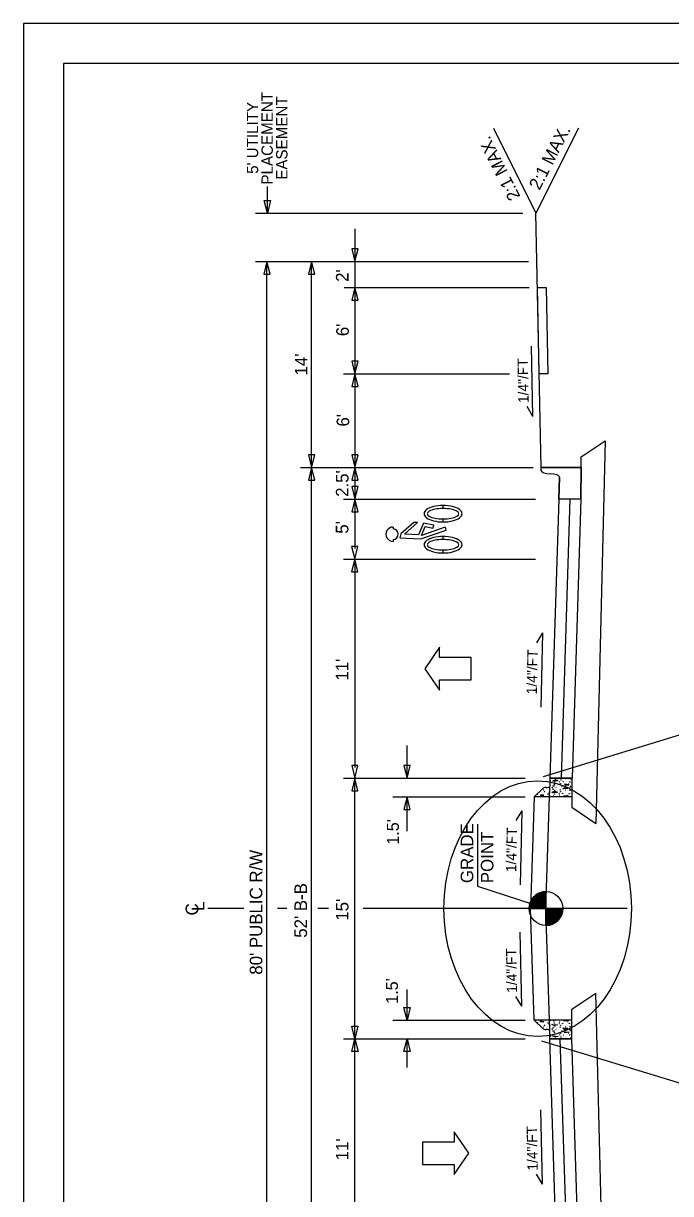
# Model space of a CAD drawing. Extents: x 0 to 8.5, y 0 to 11.
# Drawn here: x 0 to 4.02, y 3.73 to 11 of the extents above; entities that cross this region are included whole.
import ezdxf

# ---------------------------------------------------------------- set-up
doc = ezdxf.new("R2010")
doc.units = 0
for name, color, linetype in [('MARK BICYCLE SYMBOL CELL', 7, 'Continuous'), ('Old_Level_1', 7, 'Continuous'), ('Old_Level_11', 7, 'Continuous'), ('Old_Level_5', 7, 'Continuous'), ('PROP LANE ARROW CELL', 7, 'Continuous'), ('Prop Shade Light', 7, 'Continuous'), ('SHEET BORDER', 7, 'Continuous'), ('SHEET TRIM BORDER', 7, 'Continuous'), ('Typical Curb CELL', 7, 'Continuous'), ('Typical Grade Point Symbol CELL', 7, 'Continuous'), ('Typical Pavement Slope Information CELL', 7, 'Continuous')]:
    doc.layers.add(name, color=color, linetype=linetype)

msp = doc.modelspace()

# ---------------------------------------------------------------- linework, layer by layer
at = {"layer": 'MARK BICYCLE SYMBOL CELL'}
for p, q in [((2.609, 7.9845), (2.609, 8.0037)), ((2.609, 7.9845), (2.609, 8.0037)), ((2.2981, 7.8692), (2.2981, 7.8572)), ((2.2981, 7.8692), (2.2981, 7.8572)), ((2.4266, 7.8982), (2.3474, 7.8278)), ((2.3701, 7.8257), (2.451, 7.8982)), ((2.451, 7.8982), (2.4266, 7.8982)), ((2.4871, 7.8942), (2.456, 7.8205)), ((2.4743, 7.8161), (2.4981, 7.8727)), ((2.6225, 7.8683), (2.4743, 7.8161)), ((2.552, 7.8804), (2.4871, 7.8942)), ((2.4981, 7.8727), (2.5481, 7.8621)), ((2.5481, 7.8621), (2.552, 7.8804)), ((2.609, 7.9009), (2.609, 7.9201)), ((2.609, 7.9009), (2.609, 7.9201)), ((2.6287, 7.8507), (2.6245, 7.8689)), ((2.2981, 7.7924), (2.2981, 7.7804)), ((2.2981, 7.7924), (2.2981, 7.7804)), ((2.3474, 7.8278), (2.3399, 7.803)), ((2.3399, 7.803), (2.4714, 7.7953)), ((2.456, 7.8205), (2.3701, 7.8257)), ((2.4714, 7.7953), (2.6287, 7.8507)), ((2.609, 7.7916), (2.609, 7.8108)), ((2.609, 7.7916), (2.609, 7.8108)), ((2.609, 7.7081), (2.609, 7.7273)), ((2.609, 7.7081), (2.609, 7.7273))]:
    msp.add_line(p, q, dxfattribs=at)
for radius, start, end in [(0.0444, 90.00002, 270.00002), (0.0444, 90.00002, 270.00002), (0.0324, 270.00002, 90.00002)]:
    msp.add_arc((2.2981, 7.8248), radius, start, end, dxfattribs=at)
for centre, major_axis, ratio, start_param, end_param in [((2.609, 7.9523), (0.1179, 0), 0.435841, 1.570796, 4.712389), ((2.609, 7.9523), (0.1179, 0), 0.435841, 4.712389, 7.853982), ((2.609, 7.9523), (0.0987, 0), 0.325967, 1.570796, 4.712389), ((2.609, 7.9523), (0.0987, 0), 0.325967, 4.712389, 7.853982), ((2.609, 7.7594), (0.1179, 0), 0.435841, 1.570796, 4.712389), ((2.609, 7.7594), (0.0987, 0), 0.325967, 1.570796, 4.712389), ((2.609, 7.7594), (0.1179, 0), 0.435841, 4.712389, 7.853982), ((2.609, 7.7594), (0.0987, 0), 0.325967, 4.712389, 7.853982)]:
    msp.add_ellipse(centre, major_axis=major_axis, ratio=ratio, start_param=start_param, end_param=end_param, dxfattribs=at)
at = {"layer": 'Old_Level_1'}
for p, q in [((2.9224, 10.3496), (3.1867, 9.821)), ((3.4509, 10.3496), (3.1867, 9.821)), ((3.2196, 8.2386), (3.1867, 9.821)), ((3.4666, 8.3055), (3.6166, 8.4056)), ((3.6173, 8.406), (3.559, 6.0275)), ((3.4666, 8.2386), (3.4666, 8.3055)), ((3.4666, 8.2386), (3.2196, 8.2386)), ((3.2196, 8.219), (3.2196, 8.2386)), ((3.4665, 8.042), (3.4666, 8.2386)), ((3.4665, 8.042), (3.4666, 8.2386)), ((3.3331, 8.1795), (3.3287, 8.042)), ((3.3292, 8.042), (3.2727, 6.3088)), ((3.4665, 8.042), (3.3287, 8.042)), ((3.3973, 8.042), (3.3433, 6.3088)), ((3.4665, 8.042), (3.4125, 6.3088)), ((3.1749, 6.1915), (3.1531, 5.4983)), ((3.4096, 6.1915), (3.4096, 6.1271)), ((3.4096, 6.1271), (3.5596, 6.0271)), ((3.1749, 4.805), (3.1531, 5.4983)), ((3.4096, 4.8715), (3.5596, 4.9715)), ((3.6172, 2.5926), (3.559, 4.9711)), ((3.4096, 4.805), (3.4096, 4.8715)), ((3.3287, 2.9545), (3.2727, 4.6877)), ((3.393, 2.9545), (3.338, 4.6877)), ((3.4646, 2.9545), (3.4096, 4.6877))]:
    msp.add_line(p, q, dxfattribs=at)
for centre, major_axis, ratio, start_param, end_param in [((3.2784, 8.219), (0.059, 0), 0.333333, 3.141581, 4.664257), ((3.2728, 8.1797), (0.0603, 0), 0.32599, 6.272817, 7.805849)]:
    msp.add_ellipse(centre, major_axis=major_axis, ratio=ratio, start_param=start_param, end_param=end_param, dxfattribs=at)
at = {"layer": 'Old_Level_11'}
for p, q in [((1.5169, 9.821), (1.5169, 9.9854)), ((1.4438, 9.821), (3.104, 9.821)), ((2.0607, 9.7231), (2.0607, 9.2128)), ((1.4438, 9.5209), (3.1401, 9.521)), ((1.5138, 1.4756), (1.5135, 9.4997)), ((1.7921, 1.4756), (1.7921, 9.5209)), ((2.0607, 9.521), (2.0607, 9.2128)), ((1.9936, 9.3582), (3.144, 9.3583)), ((2.0607, 9.2128), (2.0607, 8.8217)), ((1.9907, 8.8216), (3.0231, 8.8217)), ((2.0607, 8.8216), (2.0607, 8.1993)), ((1.7225, 8.2386), (3.1697, 8.2386)), ((2.0607, 8.2386), (2.0606, 8.0419)), ((1.9906, 8.0419), (3.1837, 8.042)), ((2.0606, 8.0419), (2.0606, 7.7359)), ((1.9906, 7.6689), (3.1837, 7.669)), ((2.0597, 7.6689), (2.0596, 6.3754)), ((3.2343, 6.3179), (4.7141, 6.7735)), ((2.3851, 6.3082), (2.3851, 6.512)), ((1.9899, 6.3082), (3.1189, 6.3083)), ((2.0606, 4.6883), (2.0605, 6.3082)), ((3.2488, 5.4983), (3.2727, 6.2575)), ((2.2962, 6.1915), (3.1189, 6.1915)), ((2.3851, 5.9793), (2.3851, 6.1915)), ((2.8223, 6.0222), (2.8223, 5.6377)), ((2.8223, 5.6377), (3.2491, 5.4985)), ((1.3698, 5.4983), (1.1461, 5.4983)), ((1.6368, 5.4983), (1.5792, 5.4983)), ((1.8963, 5.4983), (1.8305, 5.4983)), ((3.7534, 5.4983), (2.1131, 5.4983)), ((3.2727, 4.739), (3.2488, 5.4983)), ((2.3851, 4.805), (2.3851, 4.9952)), ((2.2962, 4.805), (3.1188, 4.805)), ((1.9906, 4.6883), (3.1188, 4.6882)), ((2.0606, 3.3276), (2.0606, 4.6883)), ((2.3851, 4.5089), (2.3851, 4.6883)), ((3.221, 4.6764), (4.7706, 4.2022))]:
    msp.add_line(p, q, dxfattribs=at)
for points in [[(1.5366, 9.8996), (1.5169, 9.821), (1.4972, 9.8996)], [(2.041, 9.5996), (2.0607, 9.5209), (2.0804, 9.5996)], [(1.5335, 9.4422), (1.5138, 9.5209), (1.4941, 9.4422)], [(1.8117, 9.4422), (1.7921, 9.5209), (1.7724, 9.4422)], [(2.0804, 9.2796), (2.0607, 9.3582), (2.041, 9.2796)], [(2.041, 8.9003), (2.0607, 8.8217), (2.0803, 8.9003)], [(2.0803, 8.743), (2.0607, 8.8217), (2.041, 8.743)], [(1.7724, 8.3173), (1.7921, 8.2387), (1.8117, 8.3173)], [(2.041, 8.3173), (2.0607, 8.2386), (2.0803, 8.3173)], [(1.8118, 8.1599), (1.7921, 8.2386), (1.7724, 8.1599)], [(2.0803, 8.16), (2.0607, 8.2386), (2.041, 8.16)], [(2.041, 8.1206), (2.0606, 8.0419), (2.0803, 8.1206)], [(2.0803, 7.9632), (2.0606, 8.0419), (2.0409, 7.9632)], [(2.04, 7.7476), (2.0597, 7.6689), (2.0794, 7.7476)], [(2.0794, 7.5902), (2.0597, 7.6689), (2.04, 7.5902)], [(2.0409, 6.3869), (2.0605, 6.3082), (2.0802, 6.3869)], [(2.3654, 6.3869), (2.3851, 6.3082), (2.4048, 6.3869)], [(2.0802, 6.2296), (2.0605, 6.3082), (2.0409, 6.2296)], [(2.4048, 6.1128), (2.3851, 6.1915), (2.3654, 6.1128)], [(2.4048, 4.8837), (2.3851, 4.805), (2.3654, 4.8837)], [(2.0802, 4.7669), (2.0606, 4.6883), (2.0409, 4.7669)], [(2.0409, 4.6096), (2.0606, 4.6883), (2.0803, 4.6096)], [(2.3654, 4.6096), (2.3851, 4.6883), (2.4048, 4.6096)]]:
    msp.add_lwpolyline(points, close=True, dxfattribs=at)
msp.add_ellipse((3.1972, 5.4977), major_axis=(0.0013, -0.7944), ratio=0.733682, dxfattribs=at)
at = {"layer": 'Old_Level_5'}
for points in [[(3.2194, 8.219), (3.2196, 8.2386), (3.4666, 8.2386), (3.4665, 8.042), (3.3292, 8.042)], [(3.2757, 8.1993), (3.2756, 8.1993)], [(3.3292, 8.042), (3.3287, 8.042), (3.3331, 8.1795)]]:
    msp.add_lwpolyline(points, dxfattribs=at)
for centre, major_axis, ratio, start_param, end_param in [((3.2784, 8.219), (0.059, 0), 0.333333, 3.141581, 4.664257), ((3.2728, 8.1797), (0.0603, 0), 0.32599, 6.272817, 7.805849)]:
    msp.add_ellipse(centre, major_axis=major_axis, ratio=ratio, start_param=start_param, end_param=end_param, dxfattribs=at)
at = {"layer": 'PROP LANE ARROW CELL'}
for points in [[(2.586, 6.856), (2.586, 6.9193), (2.7832, 6.9193), (2.7832, 7.0587), (2.586, 7.0587), (2.586, 7.1221), (2.4953, 6.9877), (2.586, 6.856)], [(2.6783, 4.1099), (2.6783, 4.0465), (2.4811, 4.0465), (2.4811, 3.9071), (2.6783, 3.9071), (2.6783, 3.8438), (2.769, 3.9781), (2.6783, 4.1099)]]:
    msp.add_lwpolyline(points, dxfattribs=at)
at = {"layer": 'Prop Shade Light'}
msp.add_lwpolyline([(3.2074, 8.8217), (3.1963, 9.359), (3.2496, 9.3591), (3.2601, 8.8217)], close=True, dxfattribs=at)
at = {"layer": 'SHEET BORDER'}
msp.add_lwpolyline([(8.25, 10.75), (0.25, 10.75), (0.25, 0.25), (8.25, 0.25)], close=True, dxfattribs=at)
at = {"layer": 'SHEET TRIM BORDER'}
msp.add_lwpolyline([(8.5, 11), (0, 11), (0, 0), (8.5, 0)], close=True, dxfattribs=at)
at = {"layer": 'Typical Curb CELL'}
for p, q in [((3.2727, 6.3088), (3.4096, 6.3088)), ((3.2727, 6.3088), (3.2727, 6.2575)), ((3.4096, 6.3088), (3.2742, 6.3088)), ((3.3037, 6.2968), (3.29, 6.2904)), ((3.29, 6.2904), (3.3248, 6.2937)), ((3.3248, 6.2937), (3.3037, 6.2968)), ((3.3641, 6.2703), (3.3673, 6.2646)), ((3.3929, 6.2675), (3.3641, 6.2703)), ((3.3673, 6.2646), (3.3929, 6.2675)), ((3.4096, 6.3088), (3.4096, 6.1915)), ((3.2286, 6.2451), (3.1749, 6.1915)), ((3.4096, 6.1915), (3.1749, 6.1915)), ((3.2152, 6.203), (3.2152, 6.1963)), ((3.2354, 6.2026), (3.2152, 6.203)), ((3.2152, 6.1963), (3.2354, 6.2026)), ((3.2507, 6.2502), (3.2494, 6.2502)), ((3.3, 6.2249), (3.2863, 6.2185)), ((3.2863, 6.2185), (3.3213, 6.2217)), ((3.3213, 6.2217), (3.3, 6.2249)), ((3.3541, 6.2426), (3.3657, 6.2496)), ((3.3847, 6.245), (3.3541, 6.2426)), ((3.3604, 6.1984), (3.3636, 6.1927)), ((3.3891, 6.1956), (3.3604, 6.1984)), ((3.3636, 6.1927), (3.3891, 6.1956)), ((3.3657, 6.2496), (3.3847, 6.245)), ((3.4096, 4.805), (3.1749, 4.805)), ((3.2286, 4.7514), (3.1749, 4.805)), ((3.3604, 4.7981), (3.3636, 4.8038)), ((3.3891, 4.8009), (3.3604, 4.7981)), ((3.3636, 4.8038), (3.3891, 4.8009)), ((3.4096, 4.6877), (3.4096, 4.805)), ((3.2152, 4.7935), (3.2152, 4.8002)), ((3.2152, 4.8002), (3.2354, 4.7939)), ((3.2354, 4.7939), (3.2152, 4.7935)), ((3.2507, 4.7463), (3.2494, 4.7463)), ((3.2727, 4.6877), (3.2727, 4.739)), ((3.2863, 4.778), (3.3213, 4.7748)), ((3.3, 4.7716), (3.2863, 4.778)), ((3.3213, 4.7748), (3.3, 4.7716)), ((3.3541, 4.7539), (3.3657, 4.7469)), ((3.3847, 4.7515), (3.3541, 4.7539)), ((3.3641, 4.7262), (3.3673, 4.7319)), ((3.3929, 4.729), (3.3641, 4.7262)), ((3.3657, 4.7469), (3.3847, 4.7515)), ((3.3673, 4.7319), (3.3929, 4.729)), ((3.2727, 4.6877), (3.4096, 4.6877)), ((3.4096, 4.6877), (3.2742, 4.6877)), ((3.29, 4.7061), (3.3248, 4.7029)), ((3.3037, 4.6997), (3.29, 4.7061)), ((3.3248, 4.7029), (3.3037, 4.6997))]:
    msp.add_line(p, q, dxfattribs=at)
for centre, major_axis, start_param, end_param in [((3.2507, 6.2575), (0.022, 0), 4.712389, 6.283185), ((3.2494, 6.2428), (-0.022, 0), 4.712389, 5.961435), ((3.4082, 6.1942), (0.00149, 0), 2.042708, 4.26282), ((3.4082, 4.8023), (0.00149, 0), 2.020366, 4.240477), ((3.2494, 4.7537), (-0.022, 0), 0.321751, 1.570796), ((3.2507, 4.739), (-0.022, 0), 3.141593, 4.712389)]:
    msp.add_ellipse(centre, major_axis=major_axis, ratio=0.333333, start_param=start_param, end_param=end_param, dxfattribs=at)
for centre in [(3.2772, 6.2911), (3.2926, 6.2595), (3.2995, 6.2608), (3.3005, 6.2699), (3.3037, 6.2816), (3.308, 6.3042), (3.3345, 6.2851), (3.3376, 6.2745), (3.3408, 6.3081), (3.3419, 6.2968), (3.3472, 6.259), (3.3567, 6.2862), (3.3658, 6.2578), (3.3726, 6.3056), (3.3875, 6.2728), (3.397, 6.2841), (3.4012, 6.3046), (3.4018, 6.2578), (3.1951, 6.2079), (3.2343, 6.2355), (3.2396, 6.2249), (3.2619, 6.2101), (3.2714, 6.1973), (3.2725, 6.2341), (3.2735, 6.2192), (3.2873, 6.2489), (3.2937, 6.2394), (3.2969, 6.198), (3.3, 6.2097), (3.3043, 6.2323), (3.3107, 6.2507), (3.3308, 6.2132), (3.334, 6.2026), (3.3372, 6.2362), (3.3382, 6.2249), (3.3531, 6.2143), (3.3689, 6.2337), (3.3838, 6.2009), (3.3933, 6.2122), (3.3976, 6.2327), (3.3986, 6.2518), (3.1951, 4.7886), (3.2343, 4.761), (3.2396, 4.7716), (3.2619, 4.7864), (3.2714, 4.7992), (3.2725, 4.7624), (3.2735, 4.7773), (3.2873, 4.7476), (3.2926, 4.737), (3.2937, 4.7571), (3.2969, 4.7985), (3.2995, 4.7357), (3.3, 4.7868), (3.3043, 4.7642), (3.3107, 4.7458), (3.3308, 4.7833), (3.334, 4.7939), (3.3372, 4.7603), (3.3382, 4.7716), (3.3472, 4.7375), (3.3531, 4.7822), (3.3658, 4.7387), (3.3689, 4.7628), (3.3838, 4.7956), (3.3933, 4.7843), (3.3976, 4.7638), (3.3986, 4.7447), (3.4018, 4.7387), (3.2772, 4.7054), (3.3005, 4.7266), (3.3037, 4.7149), (3.308, 4.6923), (3.3345, 4.7114), (3.3376, 4.722), (3.3408, 4.6884), (3.3419, 4.6997), (3.3567, 4.7103), (3.3726, 4.6909), (3.3875, 4.7237), (3.397, 4.7124), (3.4012, 4.6919)]:
    msp.add_ellipse(centre, major_axis=(0.00149, 0), ratio=0.333333, dxfattribs=at)
at = {"layer": 'Typical Grade Point Symbol CELL'}
for p, q in [((3.2488, 5.6033), (3.2488, 5.4983)), ((3.2488, 5.4983), (3.1438, 5.4983)), ((3.3539, 5.498), (3.2488, 5.4983)), ((3.2488, 5.3932), (3.2488, 5.4983)), ((3.2488, 5.4983), (3.3539, 5.498))]:
    msp.add_line(p, q, dxfattribs=at)
for points in [[(3.2339, 5.6021), (3.2488, 5.6021)], [(3.1482, 5.5286), (3.2488, 5.5286)], [(3.1489, 5.5307), (3.2488, 5.5307)], [(3.1496, 5.5328), (3.2488, 5.5328)], [(3.1503, 5.5349), (3.2488, 5.5349)], [(3.1513, 5.537), (3.2488, 5.537)], [(3.1522, 5.5391), (3.2488, 5.5391)], [(3.1531, 5.5412), (3.2488, 5.5412)], [(3.1541, 5.5433), (3.2488, 5.5433)], [(3.155, 5.5454), (3.2488, 5.5454)], [(3.1562, 5.5475), (3.2488, 5.5475)], [(3.1573, 5.5496), (3.2488, 5.5496)], [(3.1585, 5.5517), (3.2488, 5.5517)], [(3.1597, 5.5538), (3.2488, 5.5538)], [(3.1611, 5.5559), (3.2488, 5.5559)], [(3.1625, 5.558), (3.2488, 5.558)], [(3.1641, 5.5601), (3.2488, 5.5601)], [(3.1655, 5.5622), (3.2488, 5.5622)], [(3.1671, 5.5643), (3.2488, 5.5643)], [(3.169, 5.5664), (3.2488, 5.5664)], [(3.1709, 5.5685), (3.2488, 5.5685)], [(3.1727, 5.5706), (3.2488, 5.5706)], [(3.1748, 5.5727), (3.2488, 5.5727)], [(3.1769, 5.5748), (3.2488, 5.5748)], [(3.1793, 5.5769), (3.2488, 5.5769)], [(3.1818, 5.579), (3.2488, 5.579)], [(3.1844, 5.5811), (3.2488, 5.5811)], [(3.1872, 5.5832), (3.2488, 5.5832)], [(3.1903, 5.5853), (3.2488, 5.5853)], [(3.1935, 5.5874), (3.2488, 5.5874)], [(3.197, 5.5895), (3.2488, 5.5895)], [(3.2007, 5.5916), (3.2488, 5.5916)], [(3.2052, 5.5937), (3.2488, 5.5937)], [(3.2101, 5.5958), (3.2488, 5.5958)], [(3.2159, 5.5979), (3.2488, 5.5979)], [(3.2232, 5.6), (3.2488, 5.6)], [(3.1438, 5.5013), (3.2488, 5.5013)], [(3.1438, 5.4992), (3.1438, 5.4992), (3.2488, 5.4992)], [(3.144, 5.5055), (3.2488, 5.5055)], [(3.144, 5.5034), (3.2488, 5.5034)], [(3.1443, 5.5076), (3.2488, 5.5076)], [(3.1445, 5.5097), (3.2488, 5.5097)], [(3.1447, 5.5118), (3.2488, 5.5118)], [(3.145, 5.5139), (3.2488, 5.5139)], [(3.1452, 5.516), (3.2488, 5.516)], [(3.1457, 5.5181), (3.2488, 5.5181)], [(3.1461, 5.5202), (3.2488, 5.5202)], [(3.1466, 5.5223), (3.2488, 5.5223)], [(3.1471, 5.5244), (3.2488, 5.5244)], [(3.1478, 5.5265), (3.2488, 5.5265)], [(3.2488, 5.4966), (3.3539, 5.4966), (3.3539, 5.4966)], [(3.2488, 5.4945), (3.3539, 5.4945)], [(3.2488, 5.4924), (3.3537, 5.4924)], [(3.2488, 5.4903), (3.3537, 5.4903)], [(3.2488, 5.4882), (3.3534, 5.4882)], [(3.2488, 5.4861), (3.3532, 5.4861)], [(3.2488, 5.484), (3.3529, 5.484)], [(3.2488, 5.4819), (3.3525, 5.4819)], [(3.2488, 5.4798), (3.3522, 5.4798)], [(3.2488, 5.4777), (3.3518, 5.4777)], [(3.2488, 5.4756), (3.3513, 5.4756)], [(3.2488, 5.4735), (3.3508, 5.4735)], [(3.2488, 5.4714), (3.3504, 5.4714)], [(3.2488, 5.4693), (3.3497, 5.4693)], [(3.2488, 5.4672), (3.3492, 5.4672)], [(3.2488, 5.4651), (3.3485, 5.4651)], [(3.2488, 5.463), (3.3478, 5.463)], [(3.2488, 5.4609), (3.3471, 5.4609)], [(3.2488, 5.4588), (3.3462, 5.4588)], [(3.2488, 5.4567), (3.3452, 5.4567)], [(3.2488, 5.4546), (3.3443, 5.4546)], [(3.2488, 5.4525), (3.3434, 5.4525)], [(3.2488, 5.4504), (3.3424, 5.4504)], [(3.2488, 5.4483), (3.3413, 5.4483)], [(3.2488, 5.4462), (3.3401, 5.4462)], [(3.2488, 5.4441), (3.3389, 5.4441)], [(3.2488, 5.442), (3.3375, 5.442)], [(3.2488, 5.4399), (3.3361, 5.4399)], [(3.2488, 5.4378), (3.3347, 5.4378)], [(3.2488, 5.4357), (3.3333, 5.4357)], [(3.2488, 5.4336), (3.3317, 5.4336)], [(3.2488, 5.4315), (3.3301, 5.4315)], [(3.2488, 5.4294), (3.3282, 5.4294)], [(3.2488, 5.4273), (3.3263, 5.4273)], [(3.2488, 5.4252), (3.3245, 5.4252)], [(3.2488, 5.4231), (3.3224, 5.4231)], [(3.2488, 5.421), (3.32, 5.421)], [(3.2488, 5.4189), (3.3177, 5.4189)], [(3.2488, 5.4168), (3.3151, 5.4168)], [(3.2488, 5.4147), (3.3126, 5.4147)], [(3.2488, 5.4126), (3.3098, 5.4126)], [(3.2488, 5.4105), (3.3067, 5.4105)], [(3.2488, 5.4084), (3.3035, 5.4084)], [(3.2488, 5.4063), (3.2997, 5.4063)], [(3.2488, 5.4042), (3.2958, 5.4042)], [(3.2488, 5.4021), (3.2913, 5.4021)], [(3.2488, 5.4), (3.2864, 5.4)], [(3.2488, 5.3979), (3.2801, 5.3979)], [(3.2488, 5.3958), (3.2726, 5.3958)], [(3.2488, 5.3937), (3.2603, 5.3937)]]:
    msp.add_lwpolyline(points, dxfattribs=at)
msp.add_circle((3.2488, 5.4981), 0.105, dxfattribs=at)
for start, end in [(89.98837, 179.98837), (269.98837, 359.98837)]:
    msp.add_arc((3.2488, 5.4981), 0.105, start, end, dxfattribs=at)
at = {"layer": 'Typical Pavement Slope Information CELL'}
for p, q in [((3.1681, 8.5572), (3.1593, 8.9943)), ((3.1681, 8.5572), (3.1311, 8.6184)), ((3.2268, 7.2111), (3.1897, 7.1498)), ((3.2268, 7.2111), (3.2175, 6.7501)), ((3.0983, 6.1057), (3.0613, 6.0445)), ((3.0983, 6.1057), (3.0891, 5.6448)), ((3.0983, 4.8908), (3.0891, 5.3518)), ((3.0983, 4.8908), (3.0613, 4.952)), ((3.2268, 3.7854), (3.2175, 4.2464)), ((3.2268, 3.7854), (3.1897, 3.8467))]:
    msp.add_line(p, q, dxfattribs=at)

# ---------------------------------------------------------------- texts
at = {"layer": 'Old_Level_11'}
for s, height, rotation, p in [('PLACEMENT', 0.07041, 90, (1.5506, 9.9982)), ("5' UTILITY", 0.07041, 90, (1.4595, 10.0648)), ('EASEMENT', 0.07041, 90, (1.6417, 10.0283)), ('2:1 MAX.', 0.07823, 62.953, (3.2087, 9.9586)), ('2:1 MAX.', 0.07823, 117.047, (3.0918, 9.9233)), ("2'", 0.07823, 89.99789, (2.0213, 9.3933)), ("6'", 0.07823, 89.99789, (2.0232, 9.0558)), ("14'", 0.07823, 90, (1.766, 8.8115)), ('1/4"/FT', 0.06402, 91.14797, (3.1413, 8.6406)), ("6'", 0.07823, 89.99789, (2.0256, 8.4941)), ("2.5'", 0.07823, 89.99789, (2.0211, 8.0568)), ("5'", 0.07823, 89.99789, (2.0206, 7.8279)), ('1/4"/FT', 0.06402, 88.85203, (3.192, 6.8292)), ("11'", 0.07823, 89.99789, (2.0204, 6.9149)), ("1.5'", 0.07502, 89.99789, (2.3345, 5.8947)), ('GRADE', 0.07823, 89.99789, (2.7969, 5.6563)), ('POINT', 0.07823, 89.99789, (2.9222, 5.6557)), ('1/4"/FT', 0.06402, 88.85203, (3.0635, 5.7239)), ("80' PUBLIC R/W", 0.078231, 90.00211, (1.4854, 5.0868)), ("52' B-B", 0.07823, 90.00211, (1.7633, 5.3163)), ('L', 0.0787, 89.94479, (1.1246, 5.4827)), ("15'", 0.07823, 89.99789, (2.021, 5.4223)), ('C', 0.0787, 89.99789, (1.0873, 5.455)), ('1/4"/FT', 0.06402, 91.14797, (3.0695, 4.9746)), ("1.5'", 0.07502, 89.99789, (2.3287, 4.9059)), ('1/4"/FT', 0.06402, 91.14797, (3.1979, 3.8692)), ("11'", 0.07823, 90.00211, (2.021, 3.9324))]:
    msp.add_text(s, height=height, rotation=rotation, dxfattribs=at).set_placement(p)

doc.saveas('drawing.dxf')
